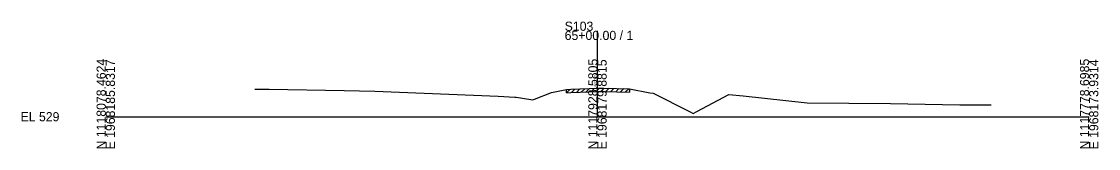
# Model space of a CAD drawing. Extents: x 974 to 1303, y 990 to 14518.
# Drawn here: x 974.3 to 1302.8, y 8990.3 to 9029.1 of the extents above; entities that cross this region are included whole.
import ezdxf

# ---------------------------------------------------------------- set-up
doc = ezdxf.new("R2010")
doc.units = 0
for name, color, linetype in [('Level 10', 7, 'Continuous'), ('Level 60', 7, 'Continuous'), ('Level 61', 7, 'Continuous'), ('Level 63', 7, 'Continuous')]:
    doc.layers.add(name, color=color, linetype=linetype)

msp = doc.modelspace()

# ---------------------------------------------------------------- linework, layer by layer
at = {"layer": 'Level 60'}
for p, q in [((1045.49, 9008.46), (1049.9, 9008.44)), ((1049.9, 9008.44), (1072.77, 9007.97)), ((1140.56, 9008.31), (1141.92, 9008.37)), ((1141.92, 9008.37), (1150.28, 9008.74)), ((1150.28, 9008.74), (1151.93, 9008.72)), ((1151.93, 9008.72), (1159.75, 9008.53)), ((1159.75, 9008.53), (1166, 9007.33)), ((1072.77, 9007.97), (1082.12, 9007.77)), ((1082.12, 9007.77), (1119.68, 9006.23)), ((1119.68, 9006.23), (1124.81, 9005.99)), ((1124.81, 9005.99), (1125.25, 9005.97)), ((1125.25, 9005.97), (1129.64, 9005.23)), ((1129.64, 9005.23), (1130.15, 9005.15)), ((1130.15, 9005.15), (1130.75, 9005.39)), ((1130.75, 9005.39), (1135.97, 9007.4)), ((1135.97, 9007.4), (1136.48, 9007.51)), ((1136.48, 9007.51), (1140.56, 9008.31)), ((1166, 9007.33), (1167.04, 9007.15)), ((1167.04, 9007.15), (1178.1, 9001.62)), ((1180.29, 9001.57), (1190.04, 9006.78)), ((1190.04, 9006.78), (1194.45, 9006.4)), ((1194.45, 9006.4), (1214.02, 9004.28)), ((1214.02, 9004.28), (1239.39, 9004.04)), ((1239.39, 9004.04), (1260.53, 9003.61)), ((1260.53, 9003.61), (1270.15, 9003.63)), ((1178.1, 9001.62), (1179.22, 9001.02)), ((1179.22, 9001.02), (1180.29, 9001.57))]:
    msp.add_line(p, q, dxfattribs=at)
at = {"layer": 'Level 61'}
for p, q in [((1142.06, 9007.37), (1143.1, 9008.42)), ((1143.56, 9007.44), (1144.6, 9008.49)), ((1145.06, 9007.51), (1146.1, 9008.55)), ((1146.56, 9007.57), (1147.6, 9008.62)), ((1148.06, 9007.64), (1149.1, 9008.69)), ((1149.56, 9007.71), (1150.58, 9008.73)), ((1151.06, 9007.73), (1152.04, 9008.72)), ((1152.56, 9007.7), (1153.53, 9008.68)), ((1154.06, 9007.67), (1155.03, 9008.64)), ((1155.56, 9007.63), (1156.53, 9008.61)), ((1157.06, 9007.6), (1158.03, 9008.57)), ((1158.56, 9007.56), (1159.53, 9008.54)), ((1159.75, 9008.53), (1159.75, 9007.53)), ((1140.56, 9007.31), (1141.6, 9008.35)), ((1140.56, 9007.31), (1140.56, 9008.31)), ((1140.56, 9007.31), (1141.92, 9007.37)), ((1140.56, 9007.31), (1140.56, 9007.31)), ((1141.92, 9007.37), (1150.28, 9007.74)), ((1150.28, 9007.74), (1151.93, 9007.72)), ((1151.93, 9007.72), (1159.75, 9007.53))]:
    msp.add_line(p, q, dxfattribs=at)
at = {"layer": 'Level 63'}
for p, q in [((1150, 9000), (1150, 9026.22)), ((1000, 9000), (1150, 9000)), ((1150, 9000), (1300, 9000))]:
    msp.add_line(p, q, dxfattribs=at)

# ---------------------------------------------------------------- texts
at = {"layer": 'Level 10'}
msp.add_text('537.73', height=0.9, rotation=90, dxfattribs=at).set_placement((1149.95, 9009.23))
at = {"layer": 'Level 63'}
for s, p in [('S103', (1140, 9026.22)), ('65+00.00 / 1', (1140, 9023.42)), ('EL 529', (974, 8998.6))]:
    msp.add_text(s, height=2.8, dxfattribs=at).set_placement(p)
for s, p in [('N 1118078.4624', (1000, 8990)), ('E 1968185.8317', (1002.8, 8990)), ('N 1117928.5805', (1150, 8990)), ('E 1968179.8815', (1152.8, 8990)), ('N 1117778.6985', (1300, 8990)), ('E 1968173.9314', (1302.8, 8990))]:
    msp.add_text(s, height=2.8, rotation=90, dxfattribs=at).set_placement(p)

doc.saveas('drawing.dxf')
